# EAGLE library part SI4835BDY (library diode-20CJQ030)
Vishay Siliconix P-Channel 30-V (D-S) MOSFET FEATURES: TrenchFET Power MOSFET Advanced High Cell Density Process 100% Rg Tested APPLICATIONS: Load Switches Notebook PCs Desktop PCs Please send any comments to: messi@users.sourceforge.net
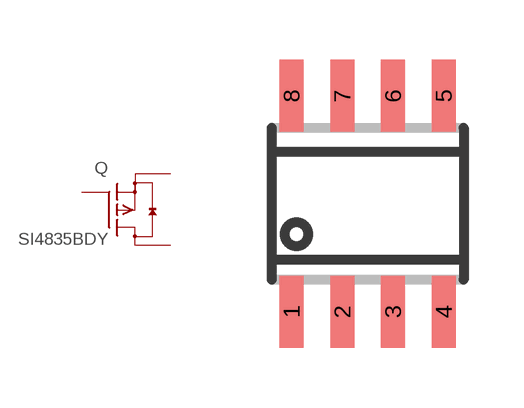
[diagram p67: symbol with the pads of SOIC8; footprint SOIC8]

Designator prefix Q

## SI4835BDY  [SOIC8]
1  S  pas
2  S  pas
3  S  pas
4  G  pas
5  D  pas
6  D  pas
7  D  pas
8  D  pas

## Footprint SOIC8 (pad centres in mm)
Small Outline IC
smd 0.6 x 1.8: 1 -1.905,-2.7; 2 -0.635,-2.7; 3 0.635,-2.7; 4 1.905,-2.7; 5 1.905,2.7; 6 0.635,2.7; 7 -0.635,2.7; 8 -1.905,2.7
